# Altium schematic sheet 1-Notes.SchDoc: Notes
size B; CompanyName: NextGen RF Design; Address1: 2130 Howard Drive W; Address2: North Mankato, MN 56003; Address3: www.nextgenrf.com; Revision: 2; SheetNumber: 1; SheetTotal: 7; ProjName: BytePipe X9002_HDK
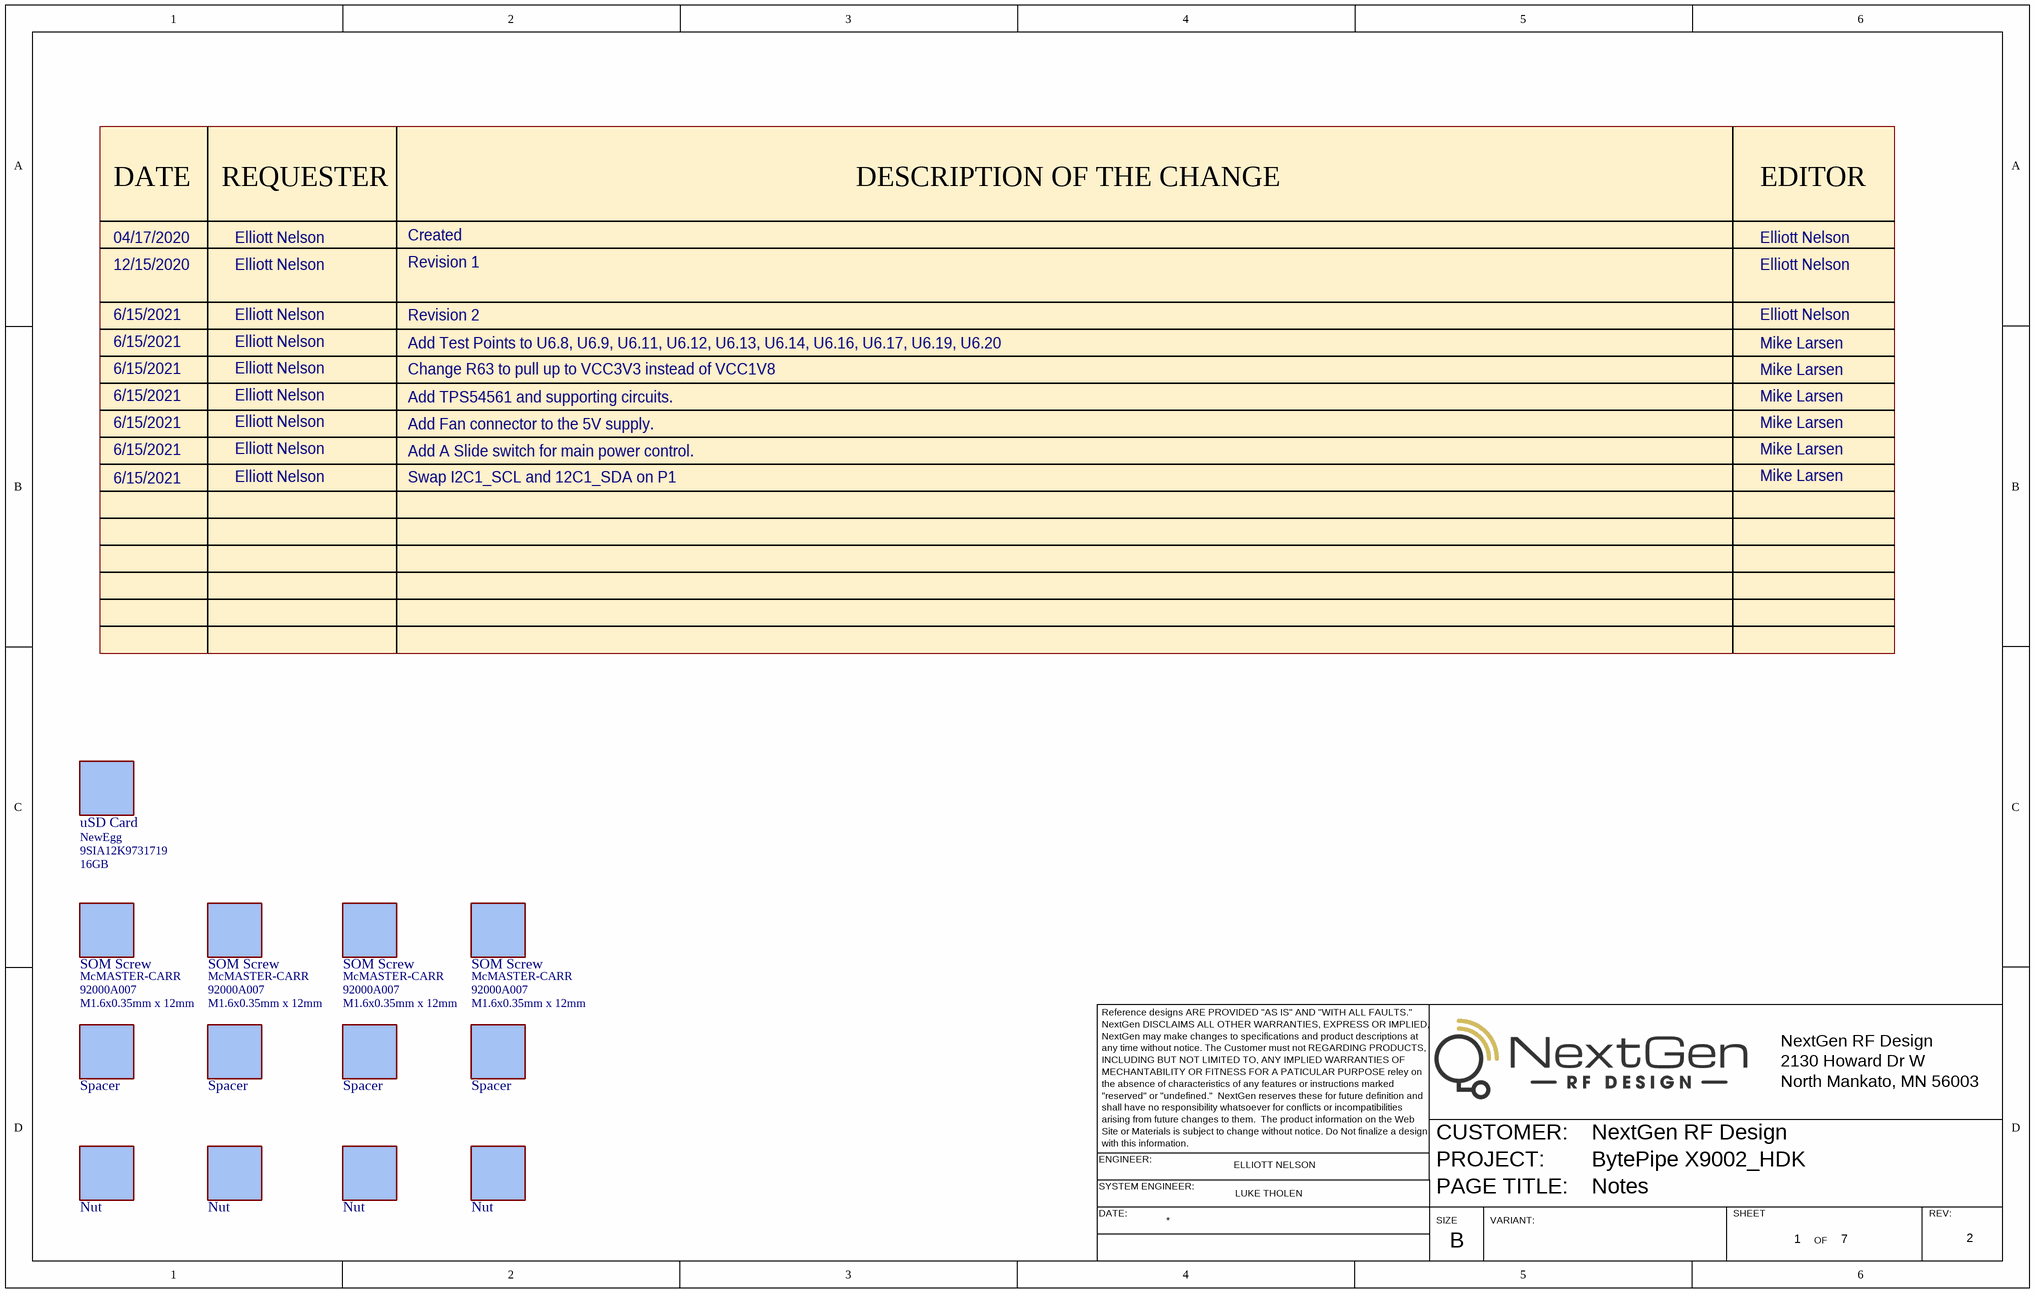
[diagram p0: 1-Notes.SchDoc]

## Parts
B1  uSD Card  value 16GB  OEM NAME: NewEgg  OEM#: 9SIA12K9731719
B2  SOM Screw  value M1.6x0.35mm x 12mm  OEM NAME: McMASTER-CARR  OEM#: 92000A007
B9  SOM Screw  value M1.6x0.35mm x 12mm  OEM NAME: McMASTER-CARR  OEM#: 92000A007
B10  SOM Screw  value M1.6x0.35mm x 12mm  OEM NAME: McMASTER-CARR  OEM#: 92000A007
B11  SOM Screw  value M1.6x0.35mm x 12mm  OEM NAME: McMASTER-CARR  OEM#: 92000A007
B12  Spacer
B13  Spacer
B14  Spacer
B15  Spacer
B20  Nut
B21  Nut
B22  Nut
B23  Nut

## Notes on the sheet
- DATE
- REQUESTER
- Created
- DESCRIPTION OF THE CHANGE
- EDITOR
- 04/17/2020
- 12/15/2020
- Elliott Nelson
- Revision 1
- 6/15/2021
- Add Test Points to U6.8, U6.9, U6.11, U6.12, U6.13, U6.14, U6.16, U6.17, U6.19, U6.20
- Change R63 to pull up to VCC3V3 instead of VCC1V8
- Revision 2
- Mike Larsen
- Add TPS54561 and supporting circuits.
- Add Fan connector to the 5V supply.
- Swap I2C1_SCL and 12C1_SDA on P1
- Add A Slide switch for main power control.
- Reference designs ARE PROVIDED "AS IS" AND "WITH ALL FAULTS."
- NextGen DISCLAIMS ALL OTHER WARRANTIES, EXPRESS OR IMPLIED,
- NextGen may make changes to specifications and product descriptions at
- NextGen RF Design
- any time without notice. The Customer must not REGARDING PRODUCTS,
- INCLUDING BUT NOT LIMITED TO, ANY IMPLIED WARRANTIES OF
- MECHANTABILITY OR FITNESS FOR A PATICULAR PURPOSE reley on
- "reserved" or "undefined."  NextGen reserves these for future definition and
- the absence of characteristics of any features or instructions marked
- shall have no responsibility whatsoever for conflicts or incompatibilities
- 2130 Howard Dr W
- North Mankato, MN 56003
- ENGINEER:
- Site or Materials is subject to change without notice. Do Not finalize a design
- with this information.
- arising from future changes to them.  The product information on the Web
- ELLIOTT NELSON
- CUSTOMER:
- PROJECT:
- SYSTEM ENGINEER:
- DATE:
- LUKE THOLEN
- SIZE
- PAGE TITLE:
- VARIANT:
- SHEET
- OF
- REV:
- B

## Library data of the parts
B1 = BOM_COMPONENT_NO-FOOTPRINT: 16GB Micro SD Memory Card Class 10 80MB/s Storage Device- BLACK
B2 B9-B15 B20-B23 = BOM_COMPONENT_NO-FOOTPRINT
